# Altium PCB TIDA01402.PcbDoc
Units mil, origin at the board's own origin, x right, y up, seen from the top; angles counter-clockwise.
Board outline 2450 x 1700 mil, 4 copper layers (Top Layer, Ground Layer, Power Layer, Bottom Layer), stack 79.834 mil thick; 49 components, 18 nets, 118 pads, 8 vias.
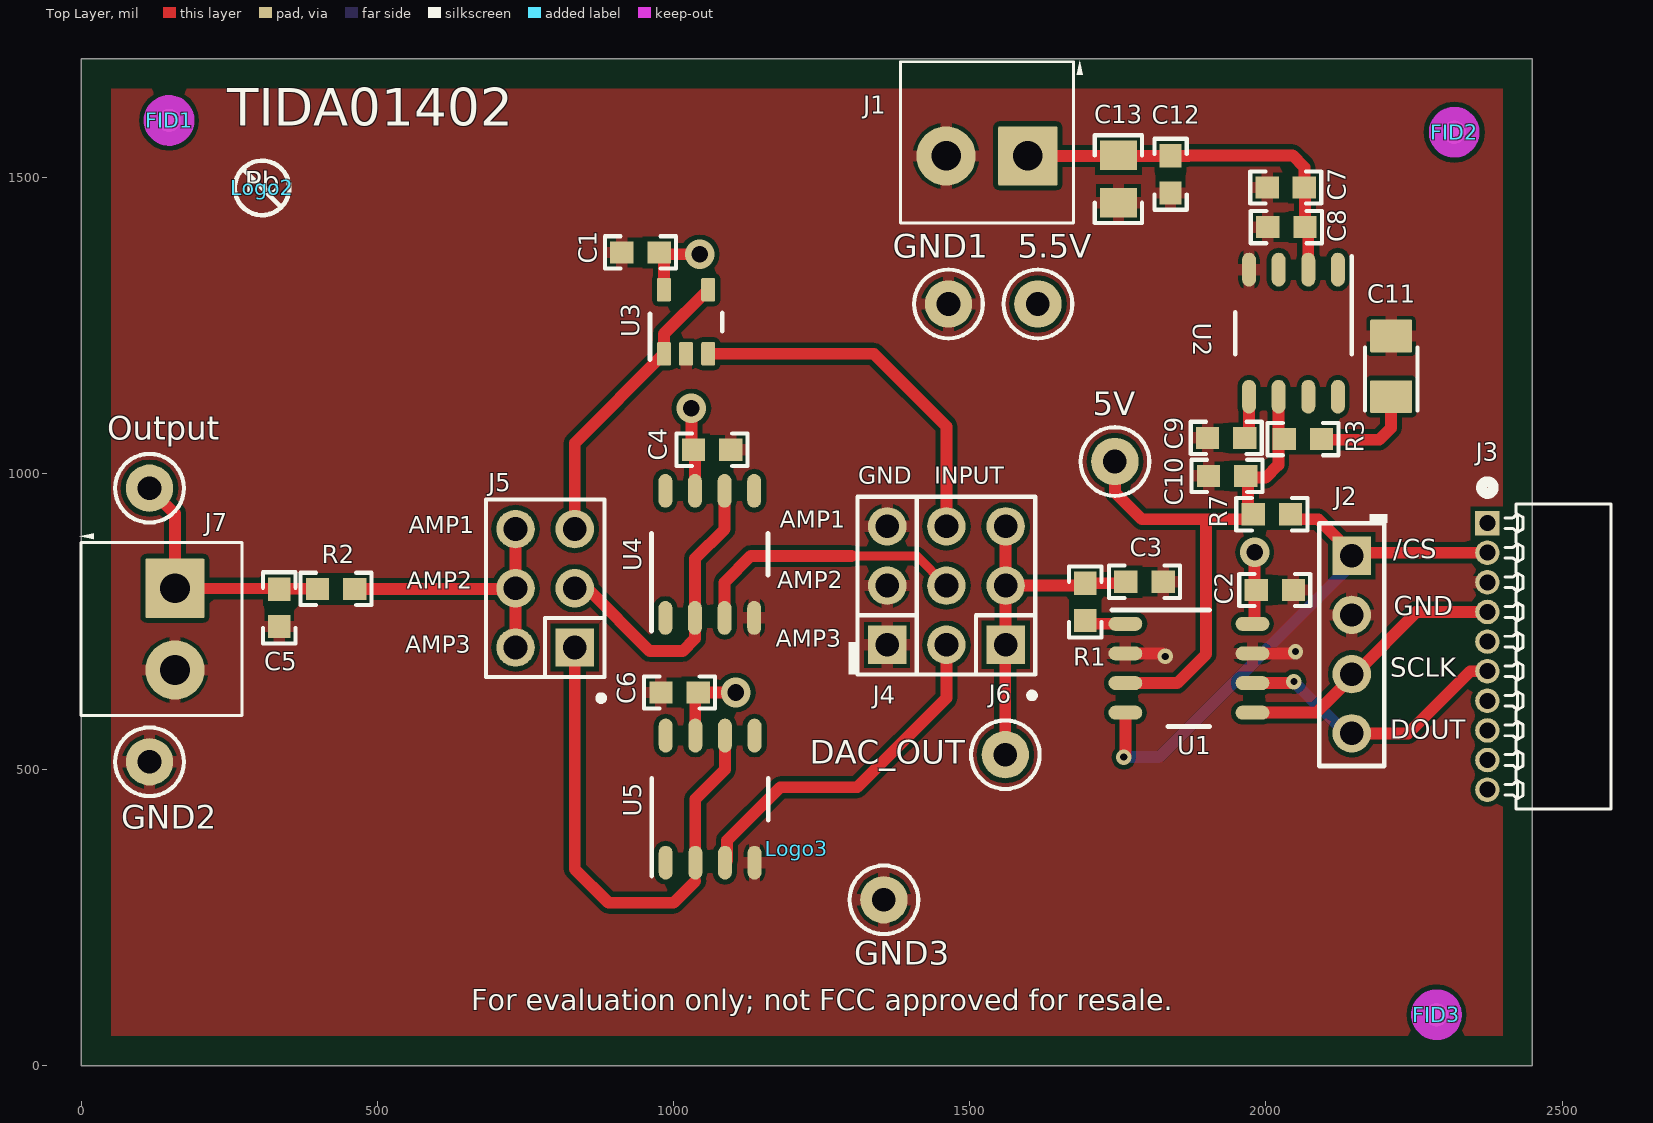
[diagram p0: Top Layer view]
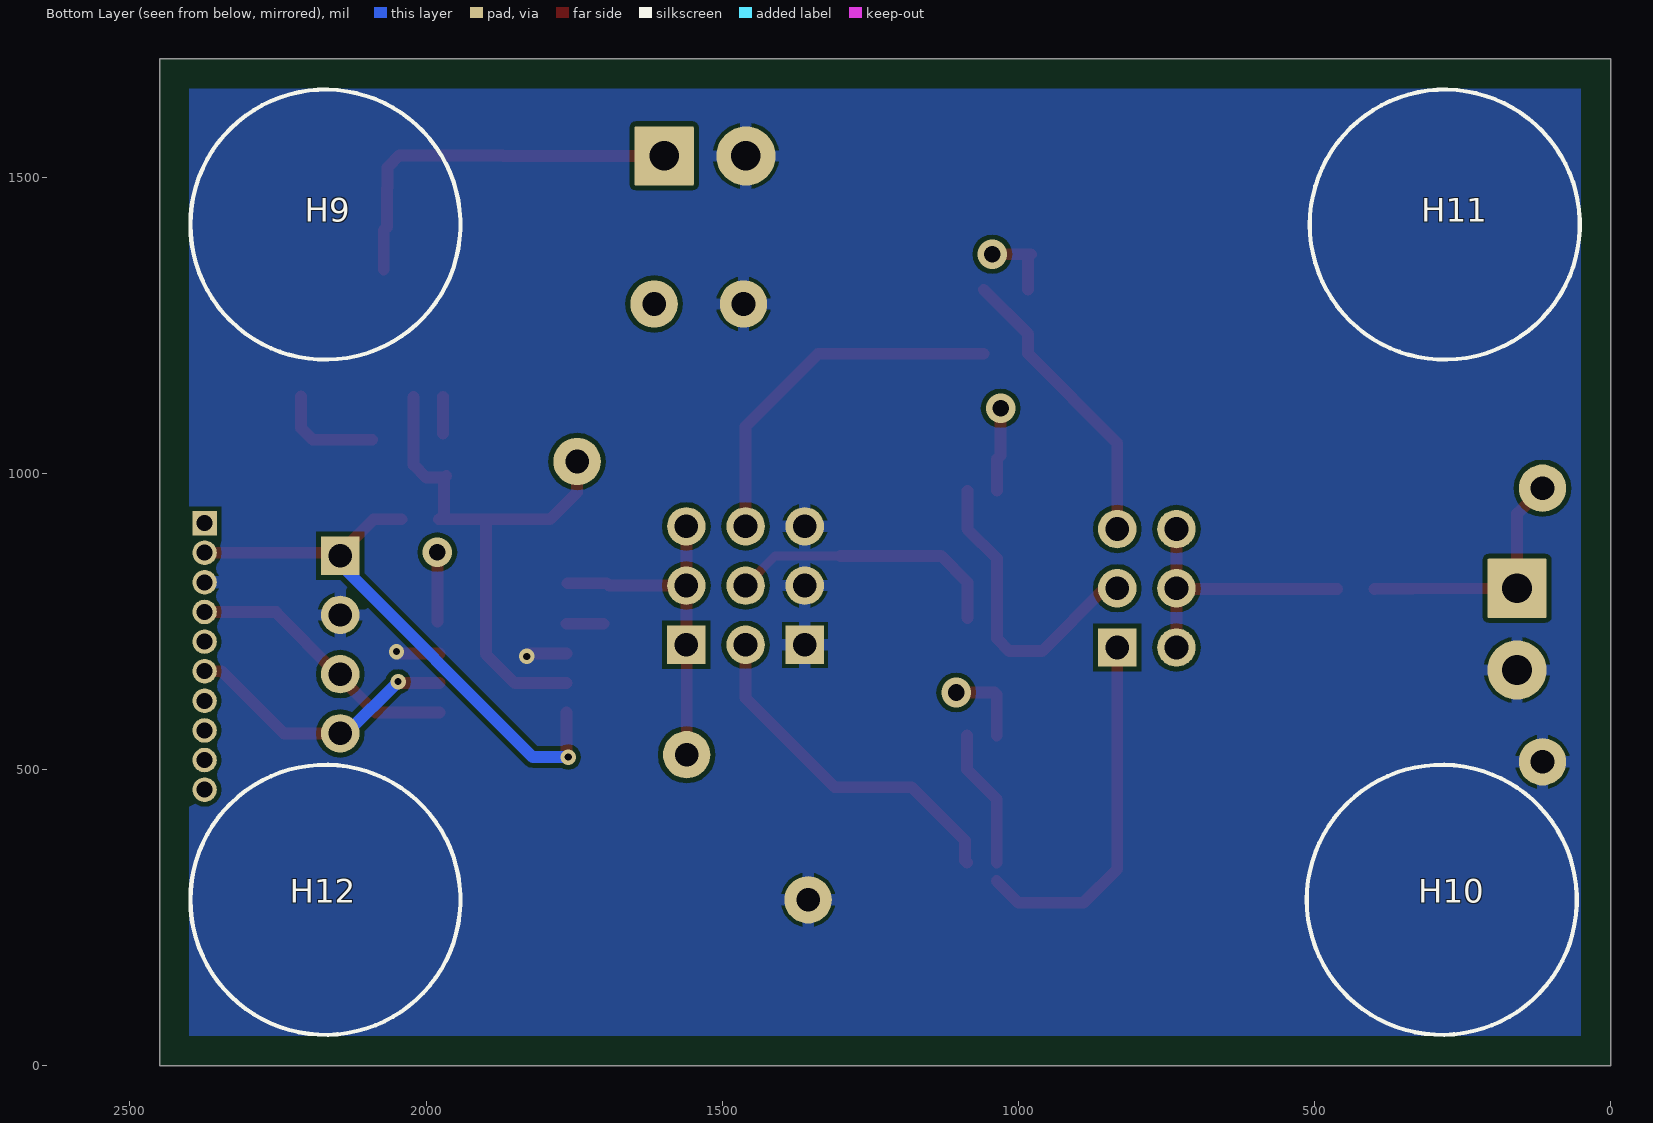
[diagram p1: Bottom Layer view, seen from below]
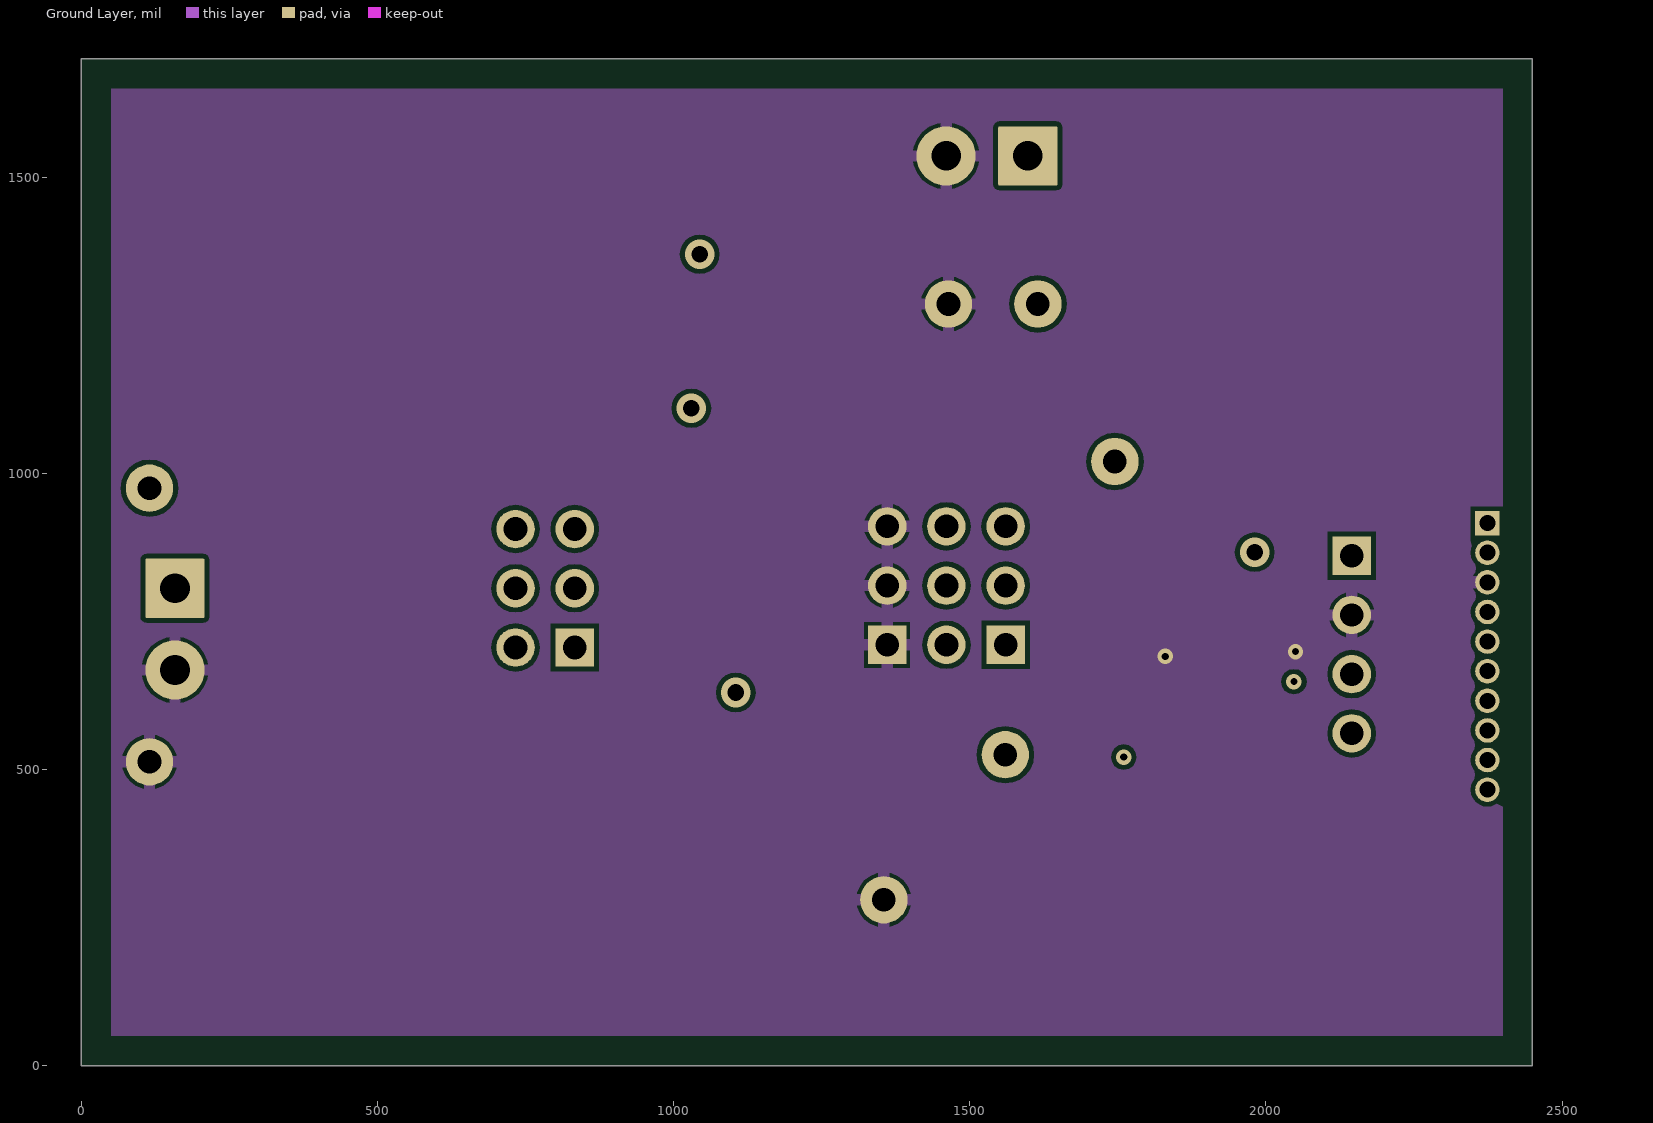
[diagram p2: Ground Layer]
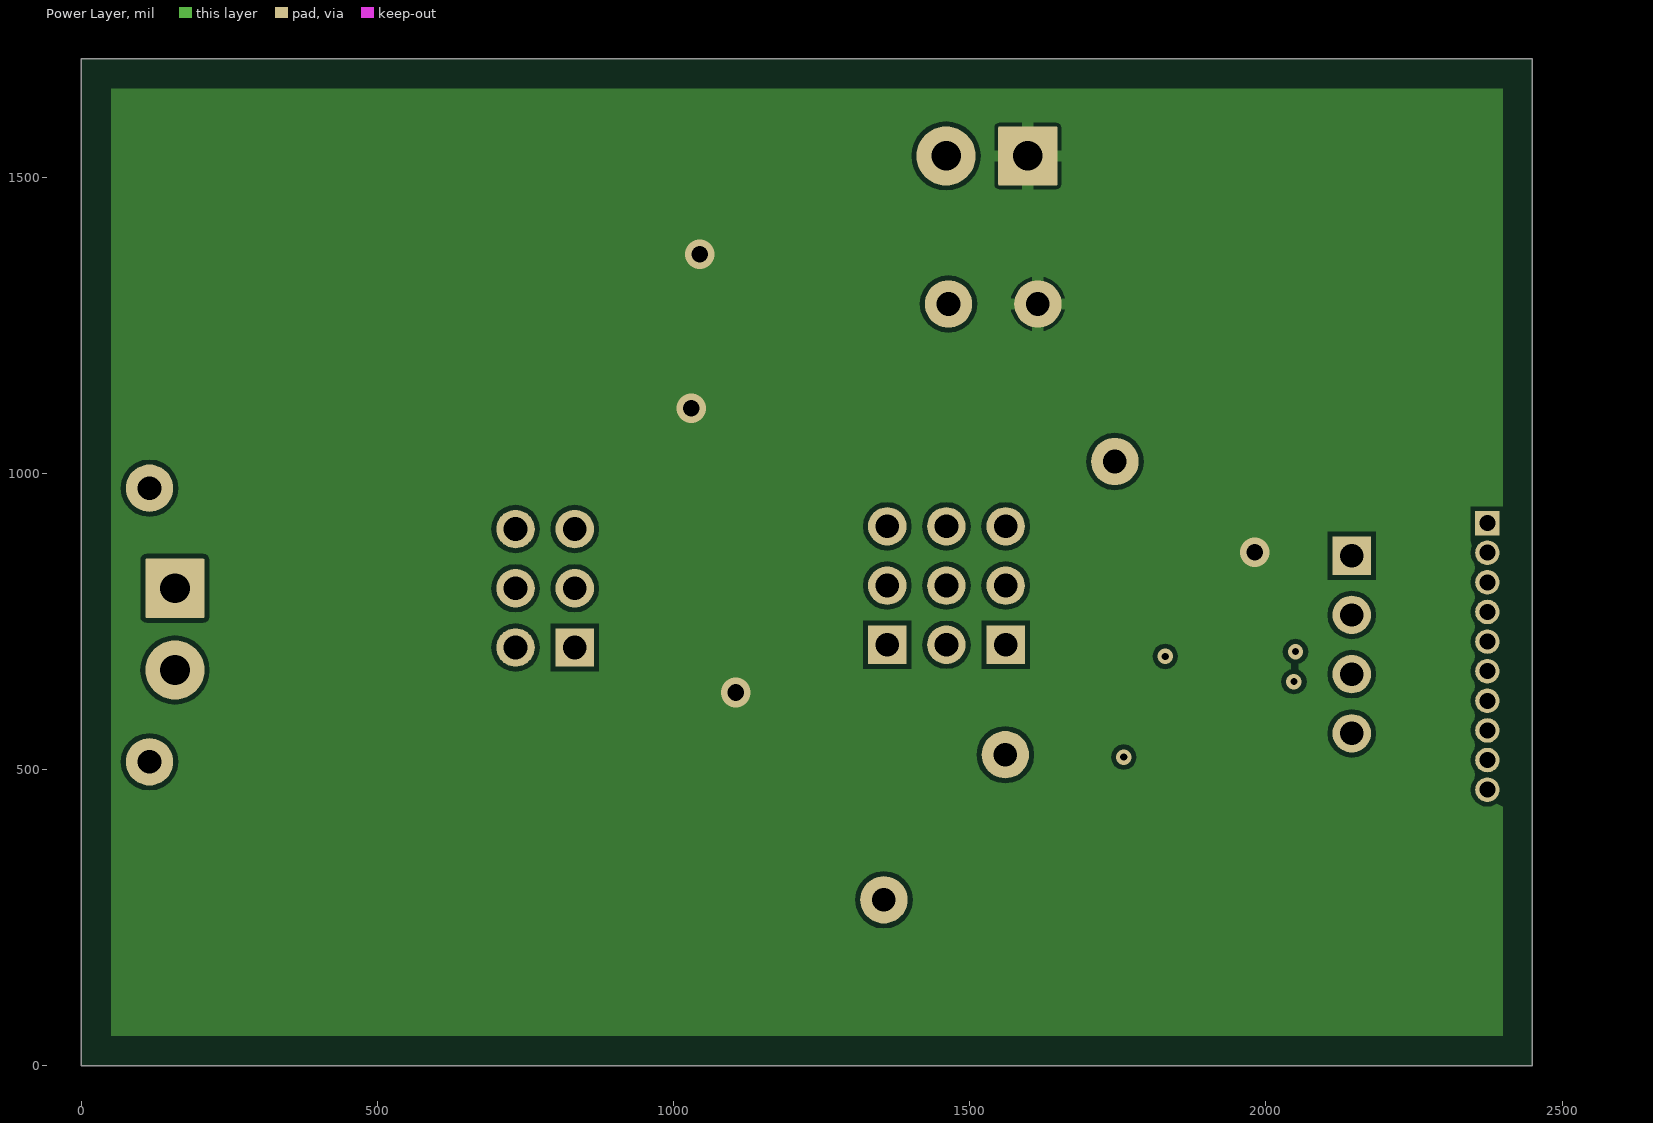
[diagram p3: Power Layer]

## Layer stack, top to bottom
Top Solder: solder mask 0.4, Solder Resist, Dk 3.5
Top Layer: signal copper 1.4
Dielectric1: core 59.2, FR-4, Dk 4.8
Ground Layer: signal copper 1.417
Dielectric 3: prepreg 5, Dk 4.2
Power Layer: signal copper 1.417
Dielectric 2: core 10, Dk 4.2
Bottom Layer: signal copper 1.4
Bottom Solder: solder mask 0.4, Solder Resist, Dk 3.5

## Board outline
0,0 0,1700 2450,1700 2450,0

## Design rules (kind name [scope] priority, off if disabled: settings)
AcuteAngle [All] p1: minimum=4.50000000000000E+0001 checktracksonly=FALSE
AssemblyTestPointUsage [All] p1: valid=2
BoardOutlineClearance BoardOutlineClearance_MountingHoles [OnCopper and InComponentClass('Mounting Holes')] p1: gap=40
BoardOutlineClearance BoardOutlineClearance_Poly [OnCopper and InPoly] p2: gap=25
BoardOutlineClearance [OnCopper and Not InComponentClass('Logo') and not InComponentClass('FiducialMark') and not InRegion(1000,500,4000,800)] p3: gap=50
Clearance Clearance_Keepouts [((IsTrack Or IsArc) And Not InPoly) And IsFree and IsKeepOut vs ((IsTrack Or IsArc) And Not InPoly) And IsFree and IsKeepOut] p1: gap=0
Clearance Clearance_Poly [InPolygon] p2: gap=8
Clearance [All] p3: gap=7.87
ComponentClearance ComponentClearance_MountingHoles_FiducialMarks [InComponentClass('Mounting Holes') vs InComponentClass('FiducialMark')] p1: gap=50 collisioncheckmode=3 verticalgap=10 showdistances=FALSE
ComponentClearance ComponentClearance_Shunt [InComponentClass('Header') vs InComponentClass('Shunt')] p2: gap=0 collisioncheckmode=3 verticalgap=0 showdistances=FALSE
ComponentClearance ComponentClearance_Logo [InComponentClass('Logo')] p3: gap=50 collisioncheckmode=3 verticalgap=10 showdistances=FALSE
ComponentClearance ComponentClearance_ScrewToNut [(HasFootprint('NY PMS 440 0025 PH')) vs (HasFootprint('Keystone_1902C'))] p4: gap=5 collisioncheckmode=3 verticalgap=10 showdistances=FALSE
ComponentClearance ComponentClearance_MountingHoles [InComponentClass('Mounting Holes')] p5: gap=250 collisioncheckmode=3 verticalgap=100000 showdistances=FALSE
ComponentClearance ComponentClearance_SmallPassives [HasFootprint('0201*') or HasFootprint('0402*') or HasFootprint('0508') or HasFootprint('0603*') or HasFootprint('0612') or HasFootprint('0805*') or HasFootprint('0815*') or HasFootprint('0830*') or HasFootprint('1206*') or HasFootprint('1210*') or HasFootprint('1808*') or HasFootprint('1812*') or HasFootprint('1825*') or HasFootprint('2010*') or HasFootprint('2220*') or HasFootprint('2225*') or HasFootprint('2512*') or HasFootprint('2728*') or HasFootprint('3518*') vs HasFootprint('0201*') or HasFootprint('0402*') or HasFootprint('0508') or HasFootprint('0603*') or HasFootprint('0612') or HasFootprint('0805*') or HasFootprint('0815*') or HasFootprint('0830*') or HasFootprint('1206*') or HasFootprint('1210*') or HasFootprint('1808*') or HasFootprint('1812*') or HasFootprint('1825*') or HasFootprint('2010*') or HasFootprint('2220*') or HasFootprint('2225*') or HasFootprint('2512*') or HasFootprint('2728*') or HasFootprint('3518*')] p6: gap=14.96 collisioncheckmode=3 verticalgap=10 showdistances=FALSE
ComponentClearance ComponentClearance_THtoSMT [IsThruComponent vs IsSMTComponent] p7: gap=40 collisioncheckmode=3 verticalgap=30 showdistances=FALSE
ComponentClearance ComponentClearance_THtoTH [IsThruComponent vs IsThruComponent] p8: gap=0 collisioncheckmode=3 verticalgap=0 showdistances=FALSE
ComponentClearance [All] p9: gap=0 collisioncheckmode=3 verticalgap=10 showdistances=FALSE
DiffPairsRouting [All] p1: maxlimit=100 minlimit=10 mostfreqgap=10 toplayer_minwidth=15 toplayer_maxwidth=15 toplayer_prefwidth=15 midlayer1_minwidth=15 midlayer1_maxwidth=15 midlayer1_prefwidth=15 midlayer2_minwidth=15 midlayer2_maxwidth=15 midlayer2_prefwidth=15 bottomlayer_minwidth=15 bottomlayer_maxwidth=15 bottomlayer_prefwidth=15 maxuncoupledlength=1000
FabricationTestPointUsage TestPointUsage [All] p1: valid=2 allowmultiple=FALSE
FabricationTestpoint Testpoint [All] p1: side=3 testpointundercomponent=TRUE minsize=40 maxsize=100 preferedsize=60 minholesize=0 maxholesize=40 preferedholesize=32 testpointgrid=1 allowsidetop=TRUE allowsidebottom=TRUE usegrid=TRUE gridtolerance=0.01
FanoutControl Fanout_LCC [IsLCC] p1: bgadir=Out bgaviamode=Centered fanoutstyle=Auto fanoutdirection=Alternating viagrid=1 // Fanout_LCC (Default Rule)
FanoutControl Fanout_BGA [IsBGA] p2: bgadir=Out bgaviamode=Centered fanoutstyle=Auto fanoutdirection=Alternating viagrid=1 // Fanout_BGA (Default Rule)
FanoutControl Fanout_Default [All] p4: bgadir=Out bgaviamode=Centered fanoutstyle=Auto fanoutdirection=Alternating viagrid=1 // Fanout_Default (Default Rule)
FanoutControl Fanout_Small [(CompPinCount < 5)] p5: bgadir=Out bgaviamode=Centered fanoutstyle=Auto fanoutdirection=OutThenIn viagrid=1 // Fanout_Small (Default Rule)
HoleSize [All] p1: absolutevalues=TRUE maxlimit=251 minlimit=7.87 maxpercent=80.000 minpercent=20.000
MinimumAnnularRing MinimumAnnularRing_ThermalPadVias [IsVia and InAnyComponent] p1: minimumring=5.91
MinimumAnnularRing [All] p2: minimumring=6
MinimumSolderMaskSliver MinimumSolderMaskSliver_Logo [InComponentClass('Logo') vs InComponentClass('Logo')] p1: minsoldermaskwidth=0.7
MinimumSolderMaskSliver [All] p2: minsoldermaskwidth=3.94
PlaneConnect [All] p1: planeconnectstyle=Relief reliefexpansion=10 reliefentries=4 reliefconductorwidth=10 reliefairgap=10
PolygonConnect PolygonConnect_1 [All vs InComponentClass('All components')] p1: connectstyle=Relief reliefconductorwidth=20 reliefentries=4 polygonreliefangle="90 Angle" airgapwidth=6
PolygonConnect [All] p2: connectstyle=Direct reliefconductorwidth=10 reliefentries=4 polygonreliefangle="90 Angle" airgapwidth=10
RoutingVias ThermalPadVias [IsVia and InAnyComponent] p1: holewidth=7.87 width=19.68 viastyle="Through Hole" minholewidth=7.87 minwidth=19.68 maxholewidth=12.99 maxwidth=23.62
RoutingVias [All] p2: holewidth=16 width=34 viastyle="Through Hole" minholewidth=8 minwidth=18 maxholewidth=40 maxwidth=65
SilkToBoardRegionClearance [Not ((IsComment or IsDesignator) And (Hide <> 'False')) and not InRegion(1000,500,4000,800)] p1:
SilkToSilkClearance SilkToSilkClearance_Pb-FreeLogo [(HasFootprint('Pb-Free_Overlay_Medium') OR HasFootprint('Pb-Free_Overlay_Small')) vs (HasFootprint('Pb-Free_Overlay_Medium') OR HasFootprint('Pb-Free_Overlay_Small'))] p1: silktosilkclearance=0
SilkToSilkClearance [All] p2: silktosilkclearance=1
SilkToSolderMaskClearance SilkToComponentPadClearance [IsPad and InAnycomponent] p1: minsilkscreentomaskgap=5 clearancetoexposedcopper=TRUE
SilkToSolderMaskClearance "Silk to Solder Mask Opening" [All] p2: minsilkscreentomaskgap=4 clearancetoexposedcopper=FALSE
SolderMaskExpansion [All] p1: expansion=1.97
Width [All] p1: maxlimit=30 minlimit=6 preferedwidth=20 checkconnectedcopper=TRUE
15 further rules are at their usual default settings.

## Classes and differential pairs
component class Header: J2 J4 J5 J6
component class TIDA01042-Schematic: 5.5V 5V BufferOutput C1 C2 C3 C4 C5 C6 C7 C8 C9 C10 C11 C12 C13 DAC_OUT GND GND1 GND2 GND3 J1 J2 J3 J4 J5 J6 J7 Output R1 R2 R3 R7 U1 U2 U3 U4 U5
component class AssemblyNote: ZZ1 ZZ2 ZZ3 ZZ4
component class FiducialMark: FID1 FID2 FID3
component class TIDA01042-Hardware: FID1 FID2 FID3 H9 H10 H11 H12 Logo2 Logo3 ZZ1 ZZ2 ZZ3 ZZ4

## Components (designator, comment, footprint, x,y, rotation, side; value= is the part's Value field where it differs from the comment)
5.5V "5000" Keystone5000 1615,1286 r0 top
5V "5000" Keystone5000 1745,1020 r0 top
C1 "06033D104KAT2A" 0603 944,1373 r0 top
C2 "06033D104KAT2A" 0603 2015,803 r0 top
C3 "GRM188R71E123KA01D" 0603 1795,817 r0 top
C4 "06033D104KAT2A" 0603 1065,1040 r180 top
C5 "GRM188R71E123KA01D" 0603 334,773 r270 top
C6 "06033D104KAT2A" 0603 1010,630 r0 top
C7 "C1608X5R1H105K080AB" 0603 2033.5,1482.78 r180 top
C8 "C1608X5R1H105K080AB" 0603 2034.5,1415.78 r180 top
C9 "C1608X5R1H105K080AB" 0603 1933,1060 r180 top
C10 "C1608X5R1H105K080AB" 0603 1934.5,995.78 r180 top
C11 "293D106X0010A2TE3" 3216-18 2211.5,1180.78 r90 top
C12 "06033D104KAT2A" 0603 1839,1505 r270 top
C13 "C2012X5R1E106K125AB" 0805_HV 1751,1497 r270 top
DAC_OUT "5002" Keystone5002 1560,525 r90 top
FID1 "Fiducial" Fiducial10-20 148,1596 r0 top
FID2 "Fiducial" Fiducial10-20 2318,1576 r0 top
FID3 "Fiducial" Fiducial10-20 2288,86 r0 top
GND1 "5001" Keystone5001 1464,1286 r0 top
GND2 "5001" Keystone5001 115,513 r0 top
GND3 "5001" Keystone5001 1355,280 r0 top
H9 "SJ-5303 (CLEAR)" Bumpon_SJ5003Transparent 2170,1420 r180 bottom
H10 "SJ-5303 (CLEAR)" Bumpon_SJ5003Transparent 285,280 r180 bottom
H11 "SJ-5303 (CLEAR)" Bumpon_SJ5003Transparent 280,1420 r180 bottom
H12 "SJ-5303 (CLEAR)" Bumpon_SJ5003Transparent 2170,280 r180 bottom
J1 "ED555/2DS" TERM_BLK_ED555-2DS 1598,1536 r180 top
J2 "PEC04SAAN" SULLINS_PEC04SAAN 2145,711 r270 top
J3 "851-43-010-20-001000" CONN_851-43-010-20-001000 2374,691 r90 top
J4 "TSW-103-07-G-S" TSW-103-07-G-S 1360.56,810.57 r90 top
J5 "TSW-103-07-G-D" TSW-103-07-G-D 783,806 r90 top
J6 "TSW-103-07-G-D" TSW-103-07-G-D 1510.56,810.57 r90 top
J7 "ED555/2DS" TERM_BLK_ED555-2DS 158,806 r270 top
Logo2 "Pb-Free Symbol" Pb-Free_Overlay_Small 305,1482 r0 top
Logo3 "FCC disclaimer" FCC_disclaimer 1208,366 r0 top
Output "5002" Keystone5002 115,975 r90 top
R1 "RC0603JR-070RL" 0603 1695,783 r90 top
R2 "RC0603JR-070RL" 0603 430,805 r180 top
R3 "RC0603JR-070RL" 0603 2062.5,1057.78 r180 top
R7 "CRCW060310K0FKEA" 0603 2010,931 r180 top
U1 "DAC8830IBDR" D0008A_N 1870,671 r0 top
U2 "REF5050AID" D0008A_N 2046.5,1236.78 r270 top
U3 "OPA333AIDBVT" DBV0005A_N 1021,1256 r90 top
U4 "OPA388IDR" D0008A_N 1061,863.28 r90 top
U5 "OPA340UA" D0008A_N 1061.57,450 r90 top
ZZ1 "This Assembly Note is for PCB labels only" AssemblyNoteLabel 245,3368 r0 top
ZZ2 "These assemblies are ESD sensitive, ESD precautions shall be observed." AssemblyNote 245,3259.11 r0 top
ZZ3 "These assemblies must be clean and free from flux and all contaminants. Use of no clean flux is not acceptable." AssemblyNote 245,3170.56 r0 top
ZZ4 "These assemblies must comply with workmanship standards IPC-A-610 Class 2, unless otherwise specified." AssemblyNote 245,3082 r0 top

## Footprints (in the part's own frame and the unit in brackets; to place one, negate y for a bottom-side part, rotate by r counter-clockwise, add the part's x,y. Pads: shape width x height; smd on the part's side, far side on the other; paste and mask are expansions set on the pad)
0603 [mm] "0603 from SM-752 data"
  rect 1x0.95 smd: 1(-0.8,0) 2(0.8,0)
  silkscreen extent -1.52,-0.69 1.52,0.69, body extent -0.87,-0.47 0.87,0.47, height 1
0805_HV [mil] "0805 with 30mil clearance between pads"
  rect 50x63 smd: 1(-40,0) 2(40,0)
  silkscreen extent -74,-40 74,40, body extent -43,-29 43,29, height 57
3216-18 [mm] "Based on AVX recommendation in http://www.avx.com/download/software/literature/AVX-Footprint-Library.pdf"
  rrect7% 1.4x1.8 smd: 1(-1.3,0) 2(1.3,0)
  silkscreen extent -1.9,-1.12 0.8,1.12, body extent -1.7,-0.9 1.7,0.9, height 1.82
AssemblyNote [mil] "Assembly Note"
AssemblyNoteLabel [mil] "Assembly Note for PCB Labels"
Bumpon_SJ5003Transparent [mil] "3M Hemispherical Bumpon transparent"
  round 1 on Mech4: 0(0,0)
  silkscreen extent -228,-228 228,228, body extent -219,-219 219,219, height 197
CONN_851-43-010-20-001000 [mm] "Mill-max"
  rect 1.05x1.05 hole 0.686 mask+0.06: 1(5.715,0)
  round 1.05 hole 0.686 mask+0.06: 2(4.445,0) 3(3.175,0) 4(1.905,0) 5(0.635,0) 6(-0.635,0) 7(-1.905,0) 8(-3.175,0) 9(-4.445,0) 10(-5.715,0)
  silkscreen extent -6.54,-5.31 7.49,0.25, body extent -6.54,-5.31 6.54,0.23, height 2.23
D0008A_N [mm] "SOIC, 8-Leads, Body 4.9x3.9mm, Pitch 1.27mm, IPC Medium Density"
  oval 1.45x0.6 smd: 1(-2.725,1.905) 2(-2.725,0.635) 3(-2.725,-0.635) 4(-2.725,-1.905) 5(2.725,-1.905) 6(2.725,-0.635) 7(2.725,0.635) 8(2.725,1.905)
  silkscreen extent -3.3,-2.5 0.9,2.5, body extent -3,-2.45 3,2.45, height 1.63
DBV0005A_N [mm] "SOT23, 5-Leads, Body 2.9x1.6mm, Pitch 0.95mm, Lead Span 2.8mm, IPC Medium Density"
  rrect17% 1x0.6 smd: 1(-1.375,0.95) 2(-1.375,0) 3(-1.375,-0.95) 4(1.375,-0.95) 5(1.375,0.95)
  silkscreen extent -1.63,-1.55 0.38,1.55, body extent -1.42,-1.46 1.42,1.46, height 1.09
FCC_disclaimer [mil]
Fiducial10-20 [mm]
  round 1 smd mask+0.5: 1(0,0)
  Top Layer keep-out circle w1.178: c0,0 r0.5
Keystone5000 [mil] "For Keystone 500x miniature loop terminals"
  round 80 hole 40: 1(0,0)
  silkscreen extent -58,-58 58,58, body extent -49,-49 49,49, height 182
Keystone5001 [mil] "For Keystone 500x miniature loop terminals"
  round 80 hole 40: 1(0,0)
  silkscreen extent -58,-58 58,58, body extent -49,-49 49,49, height 182
Keystone5002 [mil] "For Keystone 500x miniature loop terminals"
  round 80 hole 40: 1(0,0)
  silkscreen extent -58,-58 58,58, body extent -49,-49 49,49, height 182
Pb-Free_Overlay_Small [mil]
  silkscreen extent -46,-46 46,46
SULLINS_PEC04SAAN [mm] "SULLINS"
  rect 1.65x1.65 hole 1: 1(-3.81,0)
  round 1.65 hole 1: 2(-1.27,0) 3(1.27,0) 4(3.81,0)
  silkscreen extent -5.59,-1.4 5.21,1.52, body extent -5.21,-1.33 5.21,1.33, height 8.38
TERM_BLK_ED555-2DS [mil]
  rrect4% 100x100 hole 50: 1(0,0)
  round 100 hole 50: 2(138,0)
  silkscreen extent -93,-161 215,113, body extent -69,-150 207,106, height 323
TSW-103-07-G-D [mm] "Samtec 100mil, 2x3, 230 mil above insulator"
  rect 1.65x1.65 hole 1.016: 1(-2.54,-1.27)
  round 1.65 hole 1.016: 2(-2.54,1.27) 3(0,-1.27) 4(0,1.27) 5(2.54,-1.27) 6(2.54,1.27)
  silkscreen extent -4.83,-2.54 3.81,2.54, body extent -3.81,-2.54 3.81,2.54, height 8.38
TSW-103-07-G-S [mm] "Samtec 100mil, 1x3, 230 mil above insulator"
  rect 1.65x1.65 hole 1.016: 1(-2.54,0)
  round 1.65 hole 1.016: 2(0,0) 3(2.54,0)
  silkscreen extent -3.81,-1.27 3.81,1.65, body extent -3.81,-1.27 3.81,1.27, height 8.38

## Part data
5.5V 5V: "Test Point, Miniature, Red, TH"
C1 C2 C4 C6 C12: "CAP, CERM, 0.1 µF, 25 V, +/- 10%, X5R, 0603"
C3 C5: "CAP, CERM, 0.012 µF, 25 V, +/- 10%, X7R, 0603"
C7 C8 C9 C10: "CAP, CERM, 1 µF, 50 V, +/- 10%, X5R, 0603"
C11: "CAP, TA, 10 µF, 10 V, +/- 20%, 3.4 ohm, SMD"
C13: "CAP, CERM, 10 µF, 25 V, +/- 10%, X5R, 0805"
DAC_OUT Output: "Test Point, Miniature, White, TH"
FID1 FID2 FID3: "Fiducial mark.  There is nothing to buy or mount."
GND1 GND2 GND3: "Test Point, Miniature, Black, TH"
H9 H10 H11 H12: "Bumpon, Hemisphere, 0.44 X 0.20, Clear"
J1 J7: "Terminal Block, 3.5mm Pitch, 2x1, TH"
J2: "Header, 100mil, 4x1, Tin, TH"
J3: "Receptacle, 50mil, 10x1, Gold, R/A, TH"
J4: "Header, 100mil, 3x1, Gold, TH"
J5 J6: "Header, 100mil, 3x2, Gold, TH"
Logo2: library part Pb-Free
Logo3: library part FCC_disclaimer, "FCC_disclaimer"
R1 R2 R3: "RES, 0, 5%, 0.1 W, 0603"
R7: "RES, 10.0 k, 1%, 0.1 W, 0603"
U1: "16-Bit, Ultra-Low Power, Voltage-Output Digital-to-Analog Converter, D0008A (SOIC-8)"
U2: "Low Noise, Very Low Drift, Precision Voltage Reference, -40 to 125 degC, 8-pin SOIC (D), Green (RoHS & no Sb/Br)"
U3: "17 uA, MicroPower, Precision, Zero Drift CMOS Operational Amplifier, 1.8 to 5.5 V, -40 to 125 degC, 5-pin SOT23 (DBV0005A), Green (RoHS & no Sb/Br)"
U4: "Precision, Zero-Drift, Zero-Crossover, True Rail-to-Rail Input/Output, Operational Amplifier, D0008A (SOIC-8)"
U5: "Single-Supply, Rail-to-Rail Operational Amplifier MicroAmplifier(TM) Series, 2.7 to 5.5 V, -40 to 85 degC, 8-pin SOIC (D0008A), Green (RoHS & no Sb/Br)"
ZZ1: library part AssemblyNoteLabel
ZZ2 ZZ3 ZZ4: library part AssemblyNote

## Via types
v1: diameter 50, hole 28, Top Layer to Bottom Layer, 4 vias
v2: diameter 26, hole 12, Top Layer to Bottom Layer, 4 vias

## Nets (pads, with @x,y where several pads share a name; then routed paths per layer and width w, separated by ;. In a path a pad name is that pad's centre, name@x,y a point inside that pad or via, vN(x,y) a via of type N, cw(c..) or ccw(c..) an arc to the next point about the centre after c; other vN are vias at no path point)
5.5V: 5.5V.1 C1.2 C2.1 C4.2 C6.2 C7.1 C8.1 C12.1 C13.1 J1.1 U1.8 U2.2 U3.5 U4.7 U5.7 | length 1145
  Top Layer w20: C1.2@978.5,1370 v1(1044,1370) ; U3.5 C1.2@983.6,1364.9 ; C4.2@1030,1030 v1@1030,1106.22 ; U4.7 C4.2@1036,1024 ; U5.7 C6.2@1036.57,626.57 ; C6.2@1040,630 C6.2 v1(1105,630) ; J1.1 1869,1536 ; 1870,1537 2045,1537 2064.99,1517.01 C7.1 ; U1.8@1981,749.72 v1@1981,862 ; C7.1@2065.99,1481.78 C8.1 2071.5,1410.28 U2.2
  other v1: 1981,867 1030,1110
5V: 5V.1 C10.1 R3.2 R7.2 U1.3 U2.6 | length 937
  Top Layer w20: 5V.1 1745,968.06 1790.56,922.5 R7.2@1970,922.5 ; U1.3 1850,646 1899,695 1899,920.5 ; C10.1 C10.1@1968.99,992.78 ; R7.2@1978.5,922.5 R7.2@1970,922.5 ; U2.6@2021,1129 2021,1014.28 1999.5,992.78 C10.1@1968.99,992.78 ; C10.1@1968.99,992.78 1970,991.77 R7.2@1970,922.5
\CS\: J2.1 J3.2 R7.1 U1.4 | length 971.8
  Top Layer w20: v2@1762.72,523.72 U1.4 ; R7.1@2041.5,922.5 2088.5,922.5 J2.1@2150,861 ; J2.1@2145,866 J3.2
  Ground Layer w20: J2.1@2150,851.27 J2.1@2150,861
  Bottom Layer w20: v2(1760,521) 1819.73,521 J2.1@2150,851.27
"AMP1 IN": J6.6 U3.3 | length 621.7
  Top Layer w20: U3.3 1338.13,1201.87 1460.56,1079.44 J6.6
"AMP1 OUT": J5.5 U3.1 U3.4 | length 497.5
  Top Layer w20: J5.5 833,1051.27 U3.1 983.6,1235.33 U3.4
"AMP2 IN": J6.4 U4.3 | length 473.7
  Top Layer w15: 1300,860.57 1410.56,860.57 J6.4
  Top Layer w20: U4.3 1086,816 1130.57,860.57 1300,860.57
"AMP2 OUT": J5.3 U4.2 U4.6 | length 504.9
  Top Layer w20: J5.3@854,806 960,700 1015,700 1036,721 U4.2 1036,856 1086,906 U4.6
"AMP3 IN": J6.2 U5.3 | length 598.9
  Top Layer w20: U5.3 1090,346.14 1090,380 1180,470 1310,470 1460.56,620.56 J6.2
"AMP3 OUT": J5.1 U5.2 U5.6 | length 851.6
  Top Layer w20: J5.1 833,332 890,275 1000,275 1036.57,311.57 ; U5.2 1036.57,450 1086.57,500 U5.6
DOUT: J2.4 J3.6 U1.6 | length 474.1
  Top Layer w20: U1.6 v2@2045,646 ; J2.4@2150,561 2240,561 2345,666 J3.6
  Ground Layer w20: J2.4@2134.57,561 J2.4@2150,561
  Bottom Layer w20: v2(2047.28,648.28) J2.4@2134.57,561
GND: C1.1 C2.2 C3.2 C4.1 C5.2 C6.1 C7.2 C8.2 C9.2 C10.2 C11.2 C12.2 C13.2 GND1.1 GND2.1 GND3.1 J1.2 J2.2 J3.3 J4.1 J4.2 J4.3 J7.2 U1.2 U1.7 U2.4 U3.2 U4.4 U5.4 | length 139.1
  Top Layer w20: U1.2 1825,696 v2(1830,691) ; U1.7 v2@2047,696
  other v2: 2050,699
NetC3_1: C3.1 DAC_OUT.1 J6.1 J6.3 J6.5 R1.2 | length 581.5
  Top Layer w20: DAC_OUT.1 J6.1@1560,710.01 ; J6.1 J6.3 ; J6.5 J6.3 ; R1.2@1691.07,810.57 J6.3 ; R1.2 C3.1@1761,814.5
NetC5_1: C5.1 J7.1 Output.1 R2.2 | length 427.3
  Top Layer w20: Output.1 158,932 J7.1 334,805.27 R2.2
NetC9_1: C9.1 U2.5 | length 62.5
  Top Layer w20: C9.1@1971.5,1067 U2.5
NetC11_1: C11.1 R3.1 | length 181.6
  Top Layer w20: R3.1@2090.99,1056.78 2191.5,1056.78 2211.5,1076.78 C11.1
NetJ5_2: J5.2 J5.4 J5.6 R2.1 | length 458.5
  Top Layer w20: R2.1 J5.4@721,805 ; J5.2 J5.4@733,805 ; J5.4 J5.6
NetR1_1: R1.1 U1.1 | length 62.2
  Top Layer w20: R1.1@1700.5,746 U1.1
SCLK: J2.3 J3.4 U1.5 | length 469.1
  Top Layer w20: U1.5 2085,596 2150,661 2255,766 ; 2253,766 J3.4
pads on no net: FID1.1 FID2.1 FID3.1 H9.0 H10.0 H11.0 H12.0 J3.1 J3.5 J3.7 J3.8 J3.9 J3.10 U2.1 U2.3 U2.7 U2.8 U4.1 U4.5 U4.8 U5.1 U5.5 U5.8

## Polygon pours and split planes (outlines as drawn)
GND on Top Layer "TOP_LAYER_GND_P027" (solid, remove dead copper, pour order 27): 1.84,1936 2451.84,1936 2451.84,-194 2446.84,-194 2441.84,-194 1.84,-194
GND on Bottom Layer "BOTTOM_LAYER_GND_P019" (solid, remove dead copper, pour order 19): 0,-220 0,2096 2450,2096 2450,-220
GND on Ground Layer "Ground Layer" (solid, remove dead copper, pour order 31): -1,1976 2456,1976 2456,-275 2450,-269 2,-269
5.5V on Power Layer "Power Layer" (solid, remove dead copper, pour order 33): 0,1700 2450,1700 2450,7 2443,0 0,0

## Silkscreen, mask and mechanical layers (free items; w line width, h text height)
Top Overlay:
  text "TIDA01402" at 246,1566 h108.27
  text "GND" at 1312,972 h50
  text "INPUT" at 1440,972 h50
  text "AMP1" at 1179,898 h50
  text "AMP1" at 553,889 h50
  text "/CS" at 2215,846 h55
  text "AMP2" at 1175,796 h50
  text "AMP2" at 549,795 h50
  text "GND" at 2215.67,749.73 h55
  text "AMP3" at 1172,697 h50
  text "AMP3" at 547,687 h50
  text "SCLK" at 2210,646 h55
  text "DOUT" at 2210,541 h55
M1 Board Outline:
  the board outline again, w10
M2 Board Dimensions:
  rectangle: 185,-970 560,-845
  rectangle: 60,-845 185,-720
  lines w7: 60,-845 1060,-845 ; 185,-970 185,-720 ; 310,-970 310,-720 ; 560,-970 560,-720 ; 810,-970 810,-720 ; 60,-970 60,-720 1060,-720 1060,-970 60,-970
M5 Assembly Top:
  lines w10: -232,-1500.17 6368,-1500.17 ; -232,-1296.83 6370,-1296.83 ; -232,-1093.5 -232,-1703.5 3773,-1703.5 6370,-1703.5 6370,-1093.5 -231.5,-1093.5 -231.5,-1703.5 1344,-1703.5 ; 2233,-1703.5 2233,-1093.5 ; 3500,-1296.83 3500,-1093.5 ; 4340,-1296.83 4340,-1093.5 ; 4962,-1710 4962,-1507.17
  text "COMPONENTS MARKED 'DNP' SHOULD NOT BE POPULATED." at 1213.5,-888.5 h60
  text "ASSEMBLY VARIANT:" at 1213,-1004 h60
  text ".VariantName" at 2249,-1004 h60
  text "PCB VIEWED FROM TOP SIDE" at -168.5,-1225.67 h60
  text "BOARD #:" at 2308,-1225.67 h60
  text ".PRJ_Number" at 2853.5,-1225.67 h60
  text "REV:" at 3698,-1225.67 h60
  text ".PCB_Rev" at 3989.5,-1225.67 h60
  text "SVN REV:" at 4536,-1225.67 h60
  text ".VersionControl_RevNumber" at 5042,-1225.67 h60
  text "TID #:" at 2308,-1429 h60
  text ".TID" at 2853.5,-1429 h60
  text "PLOT NAME =" at -168.5,-1634.34 h60
  text ".plot_File_Name" at 637,-1634.34 h60
  text "GENERATED    :" at 2310,-1634.34 h60
  text ".Print_Date" at 3179.5,-1634.34 h60
  text ".Print_Time" at 3908.5,-1634.34 h60
  text "TEXAS INSTRUMENTS" at 5173,-1634.34 h60
M6 Assembly Bottom:
  lines w10: -232.5,-1297.33 6369.5,-1297.33 ; -230.5,-1500.67 6369.5,-1500.67 ; 1175.5,-1710.5 1175.5,-1507.67 ; 1797.5,-1297.33 1797.5,-1094 ; 2637.5,-1297.33 2637.5,-1094 ; 3904.5,-1704 3904.5,-1094 ; 4793.5,-1704 6369,-1704 6369,-1094 -232.5,-1094 -232.5,-1704 2364.5,-1704 6369.5,-1704 6369.5,-1094
  text "COMPONENTS MARKED 'DNP' SHOULD NOT BE POPULATED." at 6162,-888 h60
  text ".VariantName" at 5118,-1004 h60
  text "ASSEMBLY VARIANT:" at 6157,-1004 h60
  text ".VersionControl_RevNumber" at 1095.5,-1226.17 h60
  text "SVN REV:" at 1601.5,-1226.17 h60
  text ".PCB_Rev" at 2148,-1226.17 h60
  text "REV:" at 2439.5,-1226.17 h60
  text ".PRJ_Number" at 3284,-1226.17 h60
  text "BOARD #:" at 3829.5,-1226.17 h60
  text "PCB VIEWED FROM BOTTOM SIDE" at 6306,-1226.17 h60
  text ".TID" at 3284,-1429.5 h60
  text "TID #:" at 3829.5,-1429.5 h60
  text "TEXAS INSTRUMENTS" at 964.5,-1634.84 h60
  text ".Print_Time" at 2229,-1634.84 h60
  text ".Print_Date" at 2958,-1634.84 h60
  text "GENERATED    :" at 3827.5,-1634.84 h60
  text ".plot_File_Name" at 5500.5,-1634.84 h60
  text "PLOT NAME =" at 6306,-1634.84 h60
M9 Title Sheet:
  drawing of 57 lines, arcs and shapes, not listed
  text "1" at 799.84,7466.5 h70
  text "2" at 3295.5,7466.5 h70
  text "3" at 5784.84,7466.5 h70
  text "4" at 8291.51,7466.5 h70
  text "5" at 10790.5,7466.5 h70
  text "6" at 13295.5,7466.5 h70
  text "A" at -356.5,6323.5 h70
  text "A" at 14443.5,6323.5 h70
  text "B" at -356.5,3943.5 h70
  text "B" at 14443.5,3943.5 h70
  text "C" at -356.5,1568.5 h70
  text "C" at 14443.5,1568.5 h70
  text "PROJECT TITLE:" at 11403.5,-292.5 h45
  text "Minimizing DAC INL with zero-crossover op amp" at 11453.5,-425.83 h70
  text "DESIGNED FOR:" at 11403.5,-593.5 h45
  text "N/A" at 11453.5,-733.5 h70
  text "D" at -356.5,-801.5 h70
  text "D" at 14443.5,-801.5 h70
  text "FILE NAME:" at 11403.5,-893.5 h45
  text "TIDA01042" at 11453.5,-1013.5 h70
  text "Texas Instruments (TI) and/or its licensors do not warrant the accuracy or completeness of this specification" at 6434,-1175.34 h45
  text "ENGINEER:" at 11403.5,-1183.5 h45
  text "LAYOUT BY:" at 12908.5,-1183.5 h45
  text "or any information contained therein. TI and/or its licensors do not warrant that this design will meet" at 6389.01,-1288 h45
  text "Errol Leon" at 11453.5,-1338.49 h70
  text "Errol Leon" at 12959,-1338.49 h70
  text "the specifications, will be suitable for your application or fit for any particular purpose, or will operate in" at 6389.01,-1400.67 h45
  text ".Layer_Name" at 637,-1428.49 h60
  text "ALTIUM DESIGNER VERSION:" at 12908.5,-1493.5 h45
  text "an implementation. TI and/or its licensors do not warrant that the design is production worthy. You should" at 6389.01,-1513.33 h45
  text "completely validate and test your design implementation to confirm the system functionality for your application." at 6434,-1626 h45
  text ".print_Scale" at 11453.5,-1626.83 h70
  text "E1" at 12959,-1626.83 h70
  text "1" at 799.84,-1833.5 h70
  text "2" at 3295.5,-1833.5 h70
  text "3" at 5784.84,-1833.5 h70
  text "4" at 8291.51,-1833.5 h70
  text "5" at 10790.5,-1833.5 h70
  text "6" at 13295.5,-1833.5 h70
M10 Fab Notes:
  drawing of 173 lines, arcs and shapes, not listed
  text "DESIGN INFORMATION" at 12438.02,5631 h60
  text "MIN. TRACK WIDTH:" at 11793.46,5451 h60
  text "8" at 12889.7,5451 h60
  text "MIL" at 13044.46,5451 h60
  text "MIN. CLEARANCE:" at 11793.46,5319 h60
  text "0.2" at 12829.7,5319 h60
  text "mm" at 13044.46,5319 h60
  text "MIN. VIA PAD SIZE:" at 11793.46,5187 h60
  text "24" at 12859.71,5187 h60
  text "MIL" at 13044.46,5187 h60
  text "0.05mm (2MIL)" at 12488.46,5045.29 h60
  text "MINIMUM ANNULAR RING" at 11464.23,5041 h60
  text "EXTERNAL" at 13196.46,5041 h60
  text "PER" at 11664.23,4923 h60
  text "IPC-D-275 CLASS 2 LEVEL C" at 11884.23,4923 h60
  text "MIL, HOLES" at 13372.46,4810.71 h60
  text "+/-" at 12980,4810 h60
  text "+/-" at 13834,4810 h60
  text "REGISTRATION TOLERANCES:" at 11464.23,4805 h60
  text "METAL" at 12664,4805 h60
  text "5" at 13240.2,4805 h60
  text "3" at 14073.2,4805 h60
  text "MIL" at 14189.46,4805 h60
  text "+/-" at 13834,4692 h60
  text "HOLE SIZE TOLERANCE (UNLESS OTHERWISE SPECIFIED):" at 11464.23,4687 h60
  text "3" at 14073.2,4687 h60
  text "MIL" at 14189.46,4687 h60
  text "MATERIAL:" at 11389.46,4477.54 h60
  text "FR-4 High Tg" at 12375.9,4337.21 h60
  text "FR-408" at 11810.46,4328.64 h60
  text "OTHER" at 13298.46,4328.64 h60
  text "X" at 12221,4325 h60
  text "62 MIL (1.6mm) +/-10%" at 12130.56,4165.92 h60
  text "THICKNESS:" at 11464.23,4161.64 h60
  text "X" at 12002.4,4161.64 h60
  text "OTHER" at 13415.46,4161.64 h60
  text "TOLERANCE:" at 11464.23,4003.64 h60
  text "X" at 12303.53,4003.64 h60
  text "ANSI IPC-6012 TYPE 3 CLASS 2" at 12490.48,4003.64 h60
  text "OTHER +/-" at 12490.46,3847.64 h60
  text "BOW & TWIST:" at 11464.23,3690.64 h60
  text "X" at 12303.53,3690.64 h60
  text "ANSI IPC-6012 TYPE 3 CLASS 2" at 12490.48,3690.64 h60
  text "OTHER +/-" at 12490.46,3532.13 h60
  text "DRILLING:" at 11389.46,3393.64 h60
  text "REFERENCE:" at 11464.23,3276.64 h60
  text "X" at 12112.46,3276.64 h60
  text "AS SHOWN" at 12299.46,3276.64 h60
  text "X" at 13013.46,3276.64 h60
  text "NC_DRILL FILES" at 13150.46,3276.64 h60
  text "PTH COPPER THICKNESS:" at 11464.23,3118.64 h60
  text "X" at 12594.46,3118.64 h60
  text "20-30 um" at 12731.46,3118.64 h60
  text "OTHER" at 13448.46,3118.64 h60
  text "BOARD FINISH:" at 11389.46,2959.64 h60
  text "SILKSCREEN:" at 11544.68,2841.64 h60
  text "X" at 12493.46,2841.64 h60
  text "TOP" at 12619.46,2841.64 h60
  text "X" at 13003.46,2841.64 h60
  text "BOTTOM" at 13130.46,2841.64 h60
  text "SILKSCREEN COLOR:" at 11544.68,2674.64 h60
  text "X" at 12492.42,2674.64 h60
  text "WHITE" at 12619.46,2674.64 h60
  text "OTHER" at 13130.46,2674.64 h60
  text "X" at 12623.42,2515.44 h60
  text "GREEN" at 12750.46,2515.44 h60
  text "OTHER" at 13368.46,2515.44 h60
  text "SOLDER RESIST COLOR:" at 11544.68,2504.64 h60
  text "X" at 12623.42,2345.44 h60
  text "MATTE" at 12750.46,2345.44 h60
  text "SEMI-GLOSS" at 13368,2344.8 h60
  text "IMMERSION GOLD (ENIG)" at 12450.46,2156.92 h60
  text "ENEPIG" at 13788,2153.64 h60
  text "SURFACE FINISH:" at 11389.46,2152.64 h60
  text "X" at 12263.51,2152.64 h60
  text "IMM. TIN/SILVER OR EQUIV" at 11719,1995.64 h60
  text "OTHER" at 13150.46,1995.64 h60
  text "ARRAY/PANEL:" at 11389.46,1816.64 h60
  text "CUT AND TRIM PER M1 BOARD OUTLINE" at 12450.46,1812.35 h60
  text "N.C. ROUTE" at 12450.46,1660.64 h60
  text "X" at 13129.46,1660.64 h60
  text "V. SCORE" at 13316.46,1660.64 h60
  text "CERTIFICATION:" at 11389.46,1523.64 h60
  text "MATERIALS AND WORKMANSHIP FOR ALL PCBS" at 12114.46,1523.64 h60
  text "TO MEET OR EXCEED THE REQUIREMENTS OF:" at 12114.46,1425.64 h60
  text "X" at 11740.96,1289.13 h60
  text "ANSI IPC-A-600F CLASS ->" at 11879.96,1289.13 h60
  text "X" at 13519.02,1289.13 h60
  text "2" at 13637.96,1289.14 h60
  text "1" at 13322.96,1287.64 h60
  text "3" at 13991.96,1287.64 h60
  text "X" at 12555.02,1129.64 h60
  text "RoHS" at 12691.96,1129.64 h60
  text "OTHER" at 13336.36,1129.64 h60
  text "PER ORDER" at 13733.42,1129.64 h60
  text "ALL BOARDS MUST MEET OR EXCEED UL94-V0 REQUIREMENTS." at 11417,964 h60
  text "PCB MUST BEAR THE UL94V-0 UL REGISTERED MATERIAL ID NUMBER" at 11417,844 h60
  text "ADDITIONAL REQUIREMENTS:" at 11389.46,670.64 h60
  text "MICROSECTION:" at 11464.23,555.64 h60
  text "YES" at 12369.96,555.64 h60
  text "REQUIRED" at 13231.46,399.49 h60
  text "BARE BOARD ELEC. TEST:" at 11464.23,396.64 h60
  text "NONE" at 12769.96,396.64 h60
  text "X" at 13104.46,396.64 h60
  text "PER ORDER" at 13823.46,396.64 h60
M11 Gerber Information:
  lines w10: -232,-1500.17 6368,-1500.17 ; -232,-1296.83 6370,-1296.83 ; -232,-1093.5 -232,-1703.5 3773,-1703.5 6370,-1703.5 6370,-1093.5 -231.5,-1093.5 -231.5,-1703.5 1344,-1703.5 ; 2233,-1703.5 2233,-1093.5 ; 3500,-1296.83 3500,-1093.5 ; 4340,-1296.83 4340,-1093.5 ; 4962,-1710 4962,-1507.17
  text "ALL ARTWORK VIEWED FROM TOP SIDE" at -168.5,-1225.67 h60
  text "BOARD #:" at 2308,-1225.67 h60
  text ".PRJ_Number" at 2853.5,-1225.67 h60
  text "REV:" at 3698,-1225.67 h60
  text ".PCB_Rev" at 3989.5,-1225.67 h60
  text "SVN REV:" at 4536,-1225.67 h60
  text ".VersionControl_RevNumber" at 5042,-1225.67 h60
  text "LAYER NAME =" at -168.5,-1428.49 h60
  text "TID #:" at 2308,-1429 h60
  text ".TID" at 2853.5,-1429 h60
  text "PLOT NAME =" at -168.5,-1634.34 h60
  text ".plot_File_Name" at 637,-1634.34 h60
  text "GENERATED    :" at 2310,-1634.34 h60
  text ".Print_Date" at 3179.5,-1634.34 h60
  text ".Print_Time" at 3908.5,-1634.34 h60
  text "TEXAS INSTRUMENTS" at 5173,-1634.34 h60
M12 Stackup:
  drawing of 191 lines, arcs and shapes, not listed
  text "Layer" at 9850.34,7260 h60
  text "Name" at 10260.26,7260 h60
  text "Material" at 11190,7260 h60
  text "Thickness" at 12049.77,7260 h60
  text "Constant" at 12699.6,7260 h60
  text "Board Layer Stack" at 13269.46,7260 h60
  text "1" at 9850.34,7140 h60
  text "Top Overlay" at 10260.26,7140 h60
  text "2" at 9850.34,7020 h60
  text "Top Solder" at 10260.26,7020 h60
  text "Solder Resist" at 11190,7020 h60
  text "0.40mil" at 12049.77,7020 h60
  text "3.5" at 12699.6,7020 h60
  text "3" at 9850.34,6900 h60
  text "Top Layer" at 10260.26,6900 h60
  text "Copper" at 11190,6900 h60
  text "1.40mil" at 12049.77,6900 h60
  text "4" at 9850.34,6780 h60
  text "Dielectric1" at 10260.26,6780 h60
  text "FR-4" at 11190,6780 h60
  text "59.20mil" at 12049.77,6780 h60
  text "4.8" at 12699.6,6780 h60
  text "5" at 9850.34,6660 h60
  text "Bottom Layer" at 10260.26,6660 h60
  text "Copper" at 11190,6660 h60
  text "1.40mil" at 12049.77,6660 h60
  text "6" at 9850.34,6540 h60
  text "Bottom Solder" at 10260.26,6540 h60
  text "Solder Resist" at 11190,6540 h60
  text "0.40mil" at 12049.77,6540 h60
  text "3.5" at 12699.6,6540 h60
  text "7" at 9850.34,6420 h60
  text "Bottom Overlay" at 10260.26,6420 h60
Drill Drawing:
  lines w10: 5386.76,2212.53 5431.04,2212.53 5431.04,2256.81 5386.76,2256.81 5386.76,2212.53 ; 5386.76,2334.29 5408.9,2312.15 5431.04,2334.29 5408.9,2356.43 5386.76,2334.29 ; 5386.76,2422.84 5397.83,2422.84 5408.9,2411.77 5419.97,2422.84 5431.04,2422.84 5419.97,2433.91 5431.04,2444.98 5419.97,2444.98 5408.9,2456.05 5397.83,2444.98 5386.76,2444.98 5397.83,2433.91 5386.76,2422.84 ; 5386.76,2511.4 5408.9,2522.47 5431.04,2511.4 5419.97,2533.54 5431.04,2555.67 5408.9,2544.6 5386.76,2555.67 5397.83,2533.54 5386.76,2511.4 ; 5386.76,2611.02 5386.76,2622.09 5397.83,2633.16 5386.76,2644.23 5386.76,2655.3 5397.83,2655.3 5408.9,2644.23 5419.97,2655.3 5431.04,2655.3 5431.04,2644.23 5419.97,2633.16 5431.04,2622.09 5431.04,2611.02 5419.97,2611.02 5408.9,2622.09 5397.83,2611.02 5386.76,2611.02 ; 5386.76,2721.71 5397.83,2721.71 5397.83,2710.64 5419.97,2710.64 5419.97,2721.71 5431.04,2721.71 5431.04,2743.85 5419.97,2743.85 5419.97,2754.92 5397.83,2754.92 5397.83,2743.85 5386.76,2743.85 5386.76,2721.71
  lines w12: 5346,2182.64 8458.94,2182.64 ; 5346,2780.38 8458.94,2780.38 ; 5661.63,2083.02 5661.63,2880 ; 5978.82,2083.02 5978.82,2880 ; 6600.56,2083.02 6600.56,2880 ; 6844.88,2083.02 6844.88,2880 ; 7205.22,2083.02 7205.22,2880 ; 7914.73,2083.02 7914.73,2880 ; 5346,2083.02 8458.94,2083.02 8458.94,2880 5346,2880 5346,2083.02
  text "Symbol" at 5405.77,2810.26 h72
  text "Quantity" at 5691.52,2810.26 h72
  text "Finished Hole Size" at 6008.7,2810.26 h72
  text "Plated" at 6630.45,2810.26 h72
  text "Hole Type" at 6874.77,2810.26 h72
  text "Drill Layer Pair" at 7235.11,2810.26 h72
  text "Hole Tolerance" at 7944.62,2810.26 h72
  text "4" at 5691.52,2710.64 h60
  text "12.00mil (0.305mm)" at 6008.7,2710.64 h60
  text "PTH" at 6630.45,2710.64 h60
  text "Round" at 6874.77,2710.64 h60
  text "Top Layer - Bottom Layer" at 7235.11,2710.64 h60
  text "10" at 5691.52,2611.02 h60
  text "27.00mil (0.686mm)" at 6008.7,2611.02 h60
  text "PTH" at 6630.45,2611.02 h60
  text "Round" at 6874.77,2611.02 h60
  text "Top Layer - Bottom Layer" at 7235.11,2611.02 h60
  text "4" at 5691.52,2511.4 h60
  text "28.00mil (0.711mm)" at 6008.7,2511.4 h60
  text "PTH" at 6630.45,2511.4 h60
  text "Round" at 6874.77,2511.4 h60
  text "Top Layer - Bottom Layer" at 7235.11,2511.4 h60
  text "4" at 5691.52,2411.77 h60
  text "39.37mil (1.000mm)" at 6008.7,2411.77 h60
  text "PTH" at 6630.45,2411.77 h60
  text "Round" at 6874.77,2411.77 h60
  text "Top Layer - Bottom Layer" at 7235.11,2411.77 h60
  text "22" at 5691.52,2312.15 h60
  text "40.00mil (1.016mm)" at 6008.7,2312.15 h60
  text "PTH" at 6630.45,2312.15 h60
  text "Round" at 6874.77,2312.15 h60
  text "Top Layer - Bottom Layer" at 7235.11,2312.15 h60
  text "4" at 5691.52,2212.53 h60
  text "50.00mil (1.270mm)" at 6008.7,2212.53 h60
  text "PTH" at 6630.45,2212.53 h60
  text "Round" at 6874.77,2212.53 h60
  text "Top Layer - Bottom Layer" at 7235.11,2212.53 h60
  text "48 Total" at 5691.52,2112.91 h60

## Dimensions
0,0 to 0,1700 on M2 Board Dimensions
0,0 to 2450,0 on M2 Board Dimensions
60,-970 to 1060,-970 on M2 Board Dimensions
